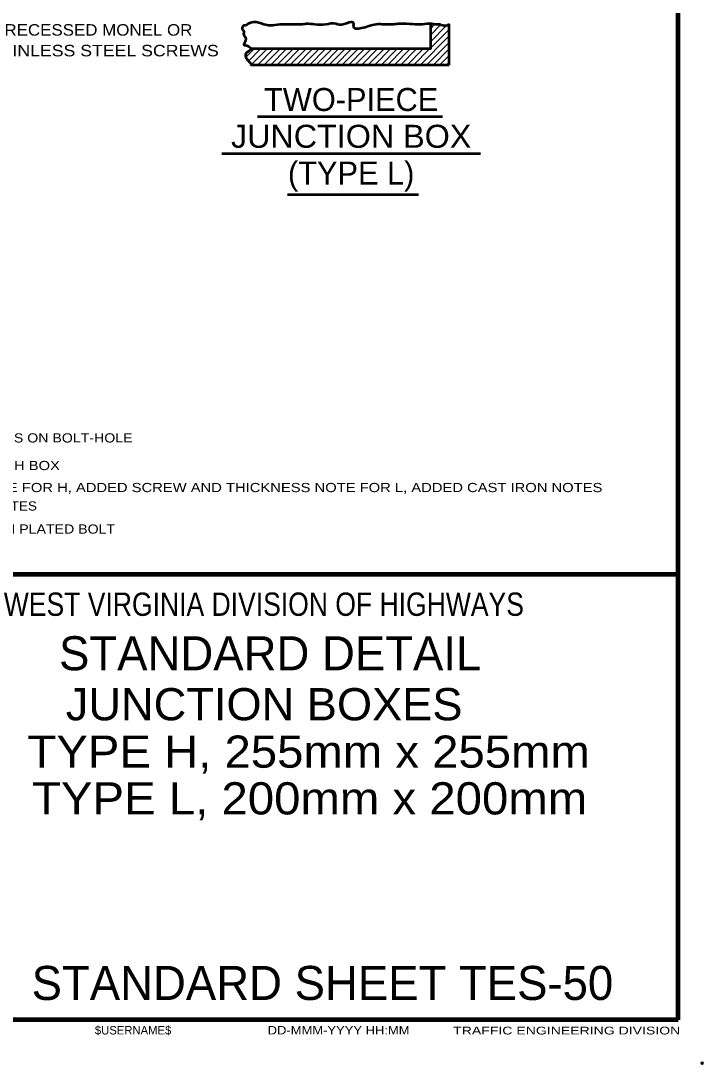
# Model space of a CAD drawing. Extents: x 442 to 1297, y -1132 to -588.
# Drawn here: x 1119.2 to 1297.3, y -1131.7 to -859.6 of the extents above; entities that cross this region are included whole.
import ezdxf
from ezdxf.enums import TextEntityAlignment as Align

# ---------------------------------------------------------------- set-up
doc = ezdxf.new("R2010")
doc.units = 0
doc.header["$LTSCALE"] = 0.96
doc.header["$PDMODE"] = 32
doc.header["$PDSIZE"] = 0.48
doc.layers.add('1', color=7, linetype='Continuous', lineweight=35)
doc.layers.add('61', color=7, linetype='Continuous', lineweight=35)

msp = doc.modelspace()

# ---------------------------------------------------------------- linework, layer by layer
at = {"layer": '1', "lineweight": 158}
for q in [(1290.7447, -594.0679), (1290.7447, -1003.8679), (499.1447, -1120.1679)]:
    msp.add_line((1290.7447, -1120.1679), q, dxfattribs=at)
at = {"layer": '1', "lineweight": 13}
msp.add_line((1290.7447, -1120.1679), (1290.7447, -594.0679), dxfattribs=at)
at = {"layer": '1'}
for p, q in [((1226.105, -861.5992), (1227.2053, -860.4989)), ((1226.105, -863.2962), (1228.7832, -860.6179)), ((1226.105, -864.9934), (1230.3271, -860.7712)), ((1226.105, -866.6904), (1230.905, -861.8903)), ((1223.3984, -871.0942), (1230.905, -863.5874)), ((1225.0955, -871.0942), (1230.905, -865.2845)), ((1178.047, -868.9285), (1180.0813, -866.8942)), ((1178.6213, -870.0512), (1181.7781, -866.8942)), ((1179.3987, -870.9708), (1183.4752, -866.8942)), ((1180.9724, -871.0942), (1185.1723, -866.8942)), ((1182.6695, -871.0942), (1186.8694, -866.8942)), ((1184.3665, -871.0942), (1188.5664, -866.8942)), ((1186.0636, -871.0942), (1190.2634, -866.8942)), ((1187.7606, -871.0942), (1191.9605, -866.8942)), ((1189.4576, -871.0942), (1193.6575, -866.8942)), ((1191.1547, -871.0942), (1195.3546, -866.8942)), ((1192.8517, -871.0942), (1197.0516, -866.8942)), ((1194.5488, -871.0942), (1198.7487, -866.8942)), ((1196.2458, -871.0942), (1200.4457, -866.8942)), ((1197.9427, -871.0942), (1202.1425, -866.8942)), ((1199.6398, -871.0942), (1203.8396, -866.8942)), ((1201.3368, -871.0942), (1205.5367, -866.8942)), ((1203.0338, -871.0942), (1207.2337, -866.8942)), ((1204.7309, -871.0942), (1208.9308, -866.8942)), ((1206.4279, -871.0942), (1210.6278, -866.8942)), ((1208.125, -871.0942), (1212.3249, -866.8942)), ((1209.822, -871.0942), (1214.0219, -866.8942)), ((1211.5191, -871.0942), (1215.719, -866.8942)), ((1213.2161, -871.0942), (1217.4159, -866.8942)), ((1214.9131, -871.0942), (1219.113, -866.8942)), ((1216.6102, -871.0942), (1220.8101, -866.8942)), ((1218.3072, -871.0942), (1222.5071, -866.8942)), ((1220.0043, -871.0942), (1224.2042, -866.8942)), ((1221.7013, -871.0942), (1225.9012, -866.8942)), ((1226.7926, -871.0942), (1230.905, -866.9816)), ((1228.4895, -871.0942), (1230.905, -868.6786)), ((1230.1865, -871.0942), (1230.905, -870.3756))]:
    msp.add_line(p, q, dxfattribs=at)
at = {"layer": '1', "lineweight": 53}
for p, q in [((1230.905, -860.2942), (1230.905, -871.0942)), ((1230.905, -871.0942), (1179.305, -871.0942)), ((1180.9826, -884.5395), (1229.2736, -884.5395)), ((1171.7166, -894.118), (1239.1643, -894.118)), ((1188.7911, -904.8415), (1223.0268, -904.8415))]:
    msp.add_line(p, q, dxfattribs=at)
msp.add_lwpolyline([(1226.105, -860.2942), (1226.105, -866.8942), (1179.305, -866.8942)], dxfattribs=at)
at = {"layer": '1', "lineweight": 158}
msp.add_lwpolyline([(1072.7447, -1120.1679), (1072.7447, -1003.8679), (1290.7447, -1003.8679)], dxfattribs=at)
at = {"layer": '1', "lineweight": 53}
msp.add_spline([(1230.905, -860.2942), (1230.4716, -860.7843), (1228.9017, -860.6416), (1228.1881, -860.4989), (1227.1891, -860.4989), (1226.105, -860.2942), (1224.0492, -860.4989), (1223.9065, -860.4989), (1222.9075, -860.4989), (1219.9104, -860.3562), (1219.6249, -860.3562), (1217.7696, -860.3562), (1216.0569, -860.4989), (1213.9161, -860.4989), (1211.9181, -860.4989), (1206.0666, -860.7843), (1206.0666, -860.0707), (1204.2112, -860.2135), (1201.9277, -860.4989), (1201.4995, -860.3562), (1198.7879, -860.4989), (1195.9335, -860.4989), (1193.7927, -860.3562), (1192.3655, -860.4989), (1189.7965, -860.4989), (1187.6557, -860.4989), (1186.7994, -860.4989), (1184.2305, -860.7843), (1182.6605, -860.4989), (1181.3761, -860.0707), (1178.5217, -860.3562), (1177.6654, -860.7843), (1177.5226, -860.7843), (1176.9518, -861.6406), (1177.3799, -862.2115), (1177.3799, -863.2106), (1177.9508, -864.2096), (1177.5226, -865.9222), (1177.6654, -865.9222), (1179.305, -866.8942), (1177.9508, -868.063), (1178.0935, -869.3475), (1178.5217, -869.9184), (1179.2353, -870.7747), (1179.305, -871.0942)], degree=3, dxfattribs=at)
at = {"layer": '1'}
msp.add_point((1297.0447, -1131.4679), dxfattribs=at)
at = {"layer": '61', "lineweight": 53}
for q in [(1138.0447, -1120.1679), (1138.0447, -1120.1679), (1138.0447, -1120.1679), (1138.3447, -1120.1679), (1138.3447, -1120.1679)]:
    msp.add_line((1290.7447, -1120.1679), q, dxfattribs=at)

# ---------------------------------------------------------------- texts
at = {"layer": '1'}
for s, height, width, p in [('RECESSED MONEL OR', 3, 1.1, (1139.4718, -863.4159)), ('STAINLESS STEEL SCREWS', 3, 1.15, (1139.4719, -868.8159)), ('JUNCTION BOX', 6, 1.05, (1205.4317, -892.668)), ('WEST VIRGINIA DIVISION OF HIGHWAYS', 6.089, 0.85, (1182.6447, -1014.7679)), ('JUNCTION BOXES', 8.4, 1.05, (1182.7198, -1042.0174)), ('TYPE H, 255mm x 255mm', 8.391, 1.1, (1194.3298, -1054.3836)), ('TYPE L, 200mm x 200mm', 8.4, 1.1, (1194.5819, -1066.573))]:
    msp.add_text(s, height=height, dxfattribs=dict(at, width=width)).set_placement(p, align=Align.CENTER)
for s, height, p in [('TWO-PIECE', 6, (1205.4317, -883.068)), ('(TYPE L)', 6, (1205.4317, -902.268)), ('STANDARD DETAIL', 8.881, (1184.2947, -1028.9679))]:
    msp.add_text(s, height=height, dxfattribs=at).set_placement(p, align=Align.CENTER)
for s, height, width, p in [('ADDED DIMENSIONS ON BOLT-HOLE', 2.4, 1.15, (1082.5548, -969.5447)), ('DELETED 3-PIECE H BOX', 2.4, 1.2, (1082.5548, -976.7447)), ('ADDED BOLT NOTE FOR H, ADDED SCREW AND THICKNESS NOTE FOR L, ADDED CAST IRON NOTES', 2.4, 1.2, (1082.0397, -982.4923)), ('AND CONCRETE NOTES', 2.4, 1.1, (1082.0397, -987.2923)), ('DELETED CADMIUM PLATED BOLT', 2.4, 1.15, (1082.0999, -993.3212)), ('DD-MMM-YYYY HH:MM', 2.2, 1.15, (1183.6447, -1123.9679)), ('TRAFFIC ENGINEERING DIVISION', 2.031, 1.35, (1232.0447, -1123.9679))]:
    msp.add_text(s, height=height, dxfattribs=dict(at, width=width)).set_placement(p)
for s, height, p in [('STANDARD SHEET TES-50', 8.881, (1122.0447, -1114.9679)), ('$USERNAME$', 2.2, (1138.5447, -1123.9679))]:
    msp.add_text(s, height=height, dxfattribs=at).set_placement(p)

doc.saveas('drawing.dxf')
